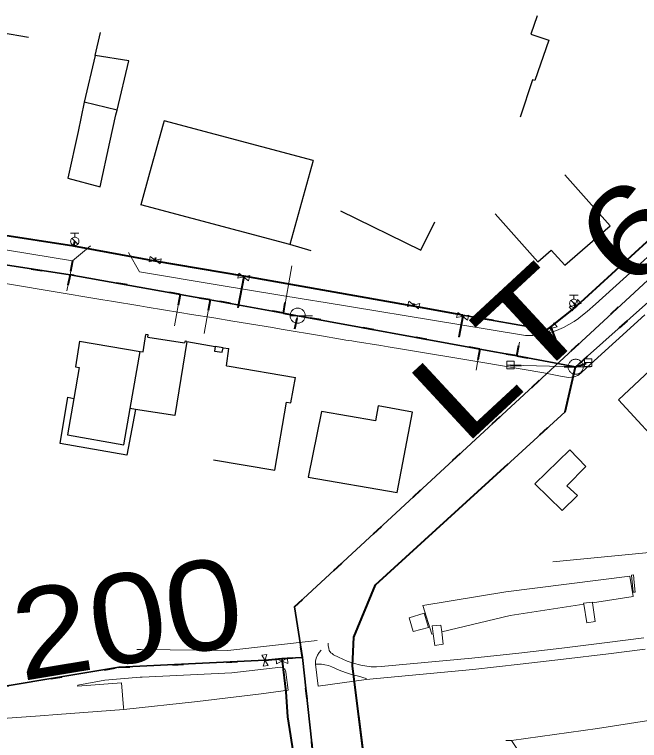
# Model space of a CAD drawing. Extents: x -968691 to -140888, y -1376050 to -879856.
# Drawn here: x -646241.5 to -646158, y -1062373.4 to -1062276.4 of the extents above; entities that cross this region are included whole.
import ezdxf
from ezdxf.enums import TextEntityAlignment as Align

# ---------------------------------------------------------------- set-up
doc = ezdxf.new("R2010")
doc.units = 0
doc.header["$LTSCALE"] = 4.8
for name, pattern in [('DASH_DOUBLE_DOT', [9.2, 5, -1.2, 0.3, -1.2, 0.3, -1.2]), ('DOT_DASHED', [7.7, 5, -1.2, 0.3, -1.2]), ('DOTTED', [1.5, 0.3, -1.2]), ('MEDIUM_DASHED', [4.5, 3, -1.5])]:
    doc.linetypes.add(name, pattern=pattern)
doc.layers.add('1', color=7, linetype='Continuous', lineweight=13)

msp = doc.modelspace()

# ---------------------------------------------------------------- linework, layer by layer
at = {"layer": '1', "lineweight": 25}
for p, q in [((-646171.665, -1062276.578), (-646172.486, -1062279.028)), ((-646239.603, -1062279.467), (-646243.221, -1062278.852)), ((-646230.719, -1062281.88), (-646232.163, -1062288.081)), ((-646227.78, -1062289.17), (-646226.21, -1062282.57)), ((-646232.163, -1062288.081), (-646232.97, -1062292.03)), ((-646227.78, -1062289.17), (-646232.163, -1062288.081)), ((-646221.476, -1062290.589), (-646221.606, -1062291.056)), ((-646201.572, -1062295.897), (-646221.476, -1062290.589)), ((-646232.97, -1062292.03), (-646234.36, -1062298.26)), ((-646171.573, -1062309.427), (-646177.286, -1062303.049)), ((-646171.573, -1062309.427), (-646169.805, -1062307.874)), ((-646169.805, -1062307.874), (-646167.951, -1062309.912)), ((-646224.288, -1062321.503), (-646223.931, -1062319.163)), ((-646223.617, -1062319.212), (-646223.931, -1062319.163)), ((-646223.668, -1062319.536), (-646223.617, -1062319.212)), ((-646232.786, -1062320.069), (-646233.36, -1062323.471)), ((-646232.786, -1062320.069), (-646224.721, -1062321.436)), ((-646223.668, -1062319.536), (-646218.77, -1062320.283)), ((-646218.447, -1062320.109), (-646214.664, -1062320.754)), ((-646213.617, -1062320.926), (-646212.864, -1062321.049)), ((-646213.185, -1062323.337), (-646212.864, -1062321.049)), ((-646226.044, -1062329.06), (-646224.721, -1062321.436)), ((-646224.721, -1062321.436), (-646224.288, -1062321.503)), ((-646233.36, -1062323.471), (-646232.857, -1062323.556)), ((-646213.185, -1062323.337), (-646212.802, -1062323.403)), ((-646212.802, -1062323.403), (-646203.969, -1062324.919)), ((-646204.553, -1062328.322), (-646203.969, -1062324.919)), ((-646188.298, -1062329.557), (-646192.897, -1062328.701)), ((-646190.36, -1062340.311), (-646188.298, -1062329.557)), ((-646165.164, -1062336.821), (-646167.692, -1062339.399)), ((-646202.24, -1062338.236), (-646190.36, -1062340.311)), ((-646168.342, -1062342.714), (-646171.987, -1062339.12)), ((-646167.692, -1062339.399), (-646166.28, -1062340.673)), ((-646166.28, -1062340.673), (-646168.342, -1062342.714))]:
    msp.add_line(p, q, dxfattribs=at)
at = {"layer": '1', "linetype": 'DASH_DOUBLE_DOT', "lineweight": 40}
for p, q in [((-646149.859, -1062300.177), (-646166.409, -1062315.397)), ((-646233.574, -1062307.333), (-646258.8, -1062303.433)), ((-646233.574, -1062307.333), (-646233.431, -1062306.701)), ((-646188.207, -1062315.382), (-646188.159, -1062315.216)), ((-646188.159, -1062315.216), (-646188.148, -1062314.999)), ((-646166.591, -1062315.224), (-646166.761, -1062314.99)), ((-646166.409, -1062315.397), (-646166.591, -1062315.224)), ((-646166.409, -1062315.397), (-646169.876, -1062318.14)), ((-646167.92, -1062329.51), (-646166.52, -1062323.48)), ((-646193.27, -1062352.65), (-646167.92, -1062329.51)), ((-646196.17, -1062359.61), (-646193.27, -1062352.65)), ((-646196.35, -1062363.51), (-646196.17, -1062359.61)), ((-646208.022, -1062362.721), (-646205.775, -1062362.467)), ((-646205.775, -1062362.467), (-646205.745, -1062362.827)), ((-646193.66, -1062384.43), (-646196.35, -1062363.51))]:
    msp.add_line(p, q, dxfattribs=at)
at = {"layer": '1', "lineweight": 35}
for p, q in [((-646149.859, -1062300.177), (-646166.409, -1062315.397)), ((-646233.574, -1062307.333), (-646258.8, -1062303.433)), ((-646246.38, -1062309.307), (-646234.073, -1062311.166)), ((-646154.258, -1062312.527), (-646166.52, -1062323.48)), ((-646205.565, -1062316.306), (-646215.343, -1062314.543)), ((-646205.565, -1062316.306), (-646203.663, -1062316.649)), ((-646166.409, -1062315.397), (-646169.876, -1062318.14)), ((-646179.311, -1062321.128), (-646203.663, -1062316.649)), ((-646174.364, -1062322.037), (-646179.311, -1062321.128)), ((-646174.364, -1062322.037), (-646166.52, -1062323.48)), ((-646205.775, -1062362.467), (-646203.013, -1062362.334))]:
    msp.add_line(p, q, dxfattribs=at)
at = {"layer": '1'}
for p, q in [((-646233.99, -1062305.632), (-646232.872, -1062305.632)), ((-646233.431, -1062306.143), (-646233.431, -1062305.632)), ((-646233.036, -1062307.097), (-646233.826, -1062306.306)), ((-646233.744, -1062309.318), (-646231.323, -1062307.33)), ((-646233.574, -1062307.333), (-646233.431, -1062306.701)), ((-646233.744, -1062309.318), (-646234.073, -1062311.166)), ((-646205.565, -1062316.306), (-646204.425, -1062309.985)), ((-646234.073, -1062311.166), (-646234.491, -1062313.345)), ((-646219.353, -1062313.82), (-646220.11, -1062318.018)), ((-646167.32, -1062313.921), (-646166.202, -1062313.921)), ((-646166.761, -1062314.432), (-646166.761, -1062313.921)), ((-646215.343, -1062314.543), (-646216.152, -1062319.027)), ((-646188.207, -1062315.382), (-646188.159, -1062315.216)), ((-646188.159, -1062315.216), (-646188.148, -1062314.999)), ((-646166.366, -1062315.386), (-646167.156, -1062314.595)), ((-646166.591, -1062315.224), (-646166.761, -1062314.99)), ((-646166.409, -1062315.397), (-646166.591, -1062315.224)), ((-646204.671, -1062316.649), (-646201.695, -1062316.649)), ((-646204.033, -1062318.409), (-646203.663, -1062316.649)), ((-646157.274, -1062316.536), (-646165.032, -1062323.593)), ((-646174.364, -1062322.037), (-646174.022, -1062320.175)), ((-646179.311, -1062321.128), (-646179.825, -1062323.921)), ((-646170.758, -1062324.308), (-646179.169, -1062322.869)), ((-646165.349, -1062322.921), (-646164.349, -1062322.921)), ((-646175.73, -1062323.25), (-646174.73, -1062323.25)), ((-646167.528, -1062323.48), (-646164.552, -1062323.48)), ((-646165.032, -1062323.593), (-646165.807, -1062324.324)), ((-646145.858, -1062347.238), (-646169.578, -1062349.572)), ((-646175.838, -1062353.59), (-646159.28, -1062351.494)), ((-646159.28, -1062351.494), (-646158.831, -1062354.207)), ((-646186.957, -1062355.413), (-646175.838, -1062353.59)), ((-646158.831, -1062354.207), (-646164.264, -1062355.04)), ((-646185.752, -1062359.219), (-646186.957, -1062355.413)), ((-646165.431, -1062355.219), (-646175.257, -1062356.726)), ((-646175.257, -1062356.726), (-646184.402, -1062358.898)), ((-646185.548, -1062359.17), (-646185.752, -1062359.219)), ((-646157.4, -1062359.7), (-646162.33, -1062360.33)), ((-646201.073, -1062360.077), (-646212.968, -1062361.433)), ((-646162.33, -1062360.33), (-646168.35, -1062361.09)), ((-646224.563, -1062361.28), (-646225.128, -1062361.273)), ((-646212.968, -1062361.433), (-646224.563, -1062361.28)), ((-646174.13, -1062361.75), (-646180.4, -1062362.43)), ((-646168.35, -1062361.09), (-646174.13, -1062361.75)), ((-646162.15, -1062361.85), (-646168.16, -1062362.59)), ((-646157.21, -1062361.23), (-646162.15, -1062361.85)), ((-646205.775, -1062362.467), (-646205.745, -1062362.827)), ((-646180.4, -1062362.43), (-646192.51, -1062363.57)), ((-646168.16, -1062362.59), (-646173.92, -1062363.26)), ((-646205.921, -1062363.644), (-646212.46, -1062364.385)), ((-646200.923, -1062366.187), (-646201.289, -1062363.243)), ((-646173.92, -1062363.26), (-646180.27, -1062363.94)), ((-646212.46, -1062364.385), (-646224.434, -1062364.974)), ((-646205.246, -1062364.293), (-646204.905, -1062366.714)), ((-646180.27, -1062363.94), (-646194.49, -1062365.29)), ((-646200.923, -1062366.187), (-646194.49, -1062365.29)), ((-646226.9, -1062369.316), (-646217.04, -1062368.217)), ((-646235.806, -1062369.99), (-646226.9, -1062369.316)), ((-646247.414, -1062370.785), (-646238.073, -1062370.161)), ((-646238.073, -1062370.161), (-646235.806, -1062369.99))]:
    msp.add_line(p, q, dxfattribs=at)
at = {"layer": '1', "linetype": 'MEDIUM_DASHED', "lineweight": 25}
for p, q in [((-646201.861, -1062307.959), (-646204.716, -1062307.146)), ((-646213.617, -1062320.926), (-646214.664, -1062320.754)), ((-646234.356, -1062327.558), (-646233.571, -1062327.704)), ((-646225.326, -1062329.193), (-646226.464, -1062335.317)), ((-646225.326, -1062329.193), (-646226.044, -1062329.06))]:
    msp.add_line(p, q, dxfattribs=at)
at = {"layer": '1', "linetype": 'DOTTED', "lineweight": 40}
for p, q in [((-646246.38, -1062309.307), (-646234.073, -1062311.166)), ((-646233.744, -1062309.318), (-646234.073, -1062311.166)), ((-646205.565, -1062316.306), (-646204.425, -1062309.985)), ((-646234.073, -1062311.166), (-646234.491, -1062313.345)), ((-646154.258, -1062312.527), (-646166.52, -1062323.48)), ((-646219.353, -1062313.82), (-646220.11, -1062318.018)), ((-646215.343, -1062314.543), (-646216.152, -1062319.027)), ((-646205.565, -1062316.306), (-646215.343, -1062314.543)), ((-646205.565, -1062316.306), (-646203.663, -1062316.649)), ((-646204.033, -1062318.409), (-646203.663, -1062316.649)), ((-646179.311, -1062321.128), (-646203.663, -1062316.649)), ((-646174.364, -1062322.037), (-646174.022, -1062320.175)), ((-646179.311, -1062321.128), (-646179.825, -1062323.921)), ((-646174.364, -1062322.037), (-646179.311, -1062321.128)), ((-646174.364, -1062322.037), (-646166.52, -1062323.48)), ((-646205.775, -1062362.467), (-646203.013, -1062362.334)), ((-646200.051, -1062389.37), (-646203.013, -1062362.334))]:
    msp.add_line(p, q, dxfattribs=at)
at = {"layer": '1', "linetype": 'DOT_DASHED', "lineweight": 25}
for p, q in [((-646214.664, -1062320.754), (-646214.759, -1062321.399)), ((-646213.736, -1062321.547), (-646213.617, -1062320.926)), ((-646214.759, -1062321.399), (-646213.736, -1062321.547))]:
    msp.add_line(p, q, dxfattribs=at)
at = {"layer": '1', "linetype": 'MEDIUM_DASHED', "lineweight": 35}
for p, q in [((-646167.92, -1062329.51), (-646166.52, -1062323.48)), ((-646193.27, -1062352.65), (-646167.92, -1062329.51)), ((-646196.17, -1062359.61), (-646193.27, -1062352.65)), ((-646196.35, -1062363.51), (-646196.17, -1062359.61))]:
    msp.add_line(p, q, dxfattribs=at)
at = {"layer": '1', "linetype": 'DOTTED', "lineweight": 40}
for points in [[(-646203.013, -1062362.334), (-646204.087, -1062355.591), (-646116.192, -1062274.176)], [(-646215.343, -1062314.543), (-646219.353, -1062313.82), (-646234.073, -1062311.166)], [(-646169.876, -1062318.14), (-646170.398, -1062318.56), (-646181.582, -1062316.571)], [(-646175.23, -1062323.25), (-646166.52, -1062323.48), (-646164.849, -1062322.921)], [(-646250.776, -1062367.517), (-646227.54, -1062363.659), (-646208.022, -1062362.721)]]:
    msp.add_lwpolyline(points, dxfattribs=at)
at = {"layer": '1', "lineweight": 35}
for points in [[(-646203.013, -1062362.334), (-646204.087, -1062355.591), (-646116.192, -1062274.176)], [(-646210.841, -1062311.363), (-646222.697, -1062309.371), (-646233.574, -1062307.333)], [(-646215.343, -1062314.543), (-646219.353, -1062313.82), (-646234.073, -1062311.166)], [(-646169.876, -1062318.14), (-646170.398, -1062318.56), (-646181.582, -1062316.571), (-646188.207, -1062315.382), (-646210.841, -1062311.363)], [(-646250.776, -1062367.517), (-646227.54, -1062363.659), (-646208.022, -1062362.721), (-646205.775, -1062362.467)], [(-646163.658, -1062633.108), (-646166.78, -1062613.779), (-646170.944, -1062588.372), (-646173.336, -1062572.987), (-646174.283, -1062562.133), (-646181.259, -1062514.067), (-646183, -1062500.862), (-646184.952, -1062489.727), (-646187.355, -1062471.952), (-646188.163, -1062467.368), (-646192.754, -1062436.977), (-646194.767, -1062423.918), (-646197.934, -1062403.993), (-646200.051, -1062389.37), (-646203.013, -1062362.334)]]:
    msp.add_lwpolyline(points, dxfattribs=at)
at = {"layer": '1', "lineweight": 25}
for points in [[(-646226.21, -1062282.57), (-646230.719, -1062281.88), (-646230.014, -1062278.805)], [(-646172.486, -1062279.028), (-646170.121, -1062279.821), (-646171.978, -1062285.193), (-646172.274, -1062285.126), (-646173.949, -1062290.125)], [(-646228.76, -1062293.43), (-646227.93, -1062289.78), (-646227.78, -1062289.17)], [(-646221.606, -1062291.056), (-646223.431, -1062297.582), (-646224.62, -1062301.838)], [(-646234.36, -1062298.26), (-646230.061, -1062299.403), (-646228.76, -1062293.43)], [(-646201.572, -1062295.897), (-646204.716, -1062307.146), (-646224.62, -1062301.838)], [(-646167.951, -1062309.912), (-646161.923, -1062304.62), (-646167.973, -1062297.824)], [(-646197.939, -1062302.651), (-646187.188, -1062307.907), (-646185.316, -1062304.09)], [(-646218.447, -1062320.109), (-646220.049, -1062329.991), (-646225.326, -1062329.193)], [(-646218.447, -1062320.109), (-646218.708, -1062320.053), (-646218.77, -1062320.283)], [(-646154.073, -1062335.203), (-646160.786, -1062327.92), (-646153.81, -1062321.348)], [(-646232.857, -1062323.556), (-646233.571, -1062327.704), (-646234.41, -1062332.575), (-646226.89, -1062333.933), (-646226.044, -1062329.06)], [(-646214.891, -1062335.902), (-646206.716, -1062337.286), (-646205.163, -1062328.217), (-646204.553, -1062328.322)], [(-646192.897, -1062328.701), (-646193.263, -1062330.694), (-646200.495, -1062329.447), (-646202.24, -1062338.236)], [(-646171.987, -1062339.12), (-646167.318, -1062334.595), (-646165.164, -1062336.821)]]:
    msp.add_lwpolyline(points, dxfattribs=at)
at = {"layer": '1'}
for points in [[(-646166.062, -1062316.93), (-646164.978, -1062316.111), (-646163.869, -1062315.12), (-646157.426, -1062309.252), (-646149.103, -1062301.676), (-646143.832, -1062296.861)], [(-646258.703, -1062301.449), (-646258.683, -1062301.767), (-646258.572, -1062302.212), (-646258.272, -1062303.02), (-646257.788, -1062303.975), (-646257.294, -1062304.622), (-646256.702, -1062305.143), (-646256.086, -1062305.503), (-646255.105, -1062305.789), (-646248.165, -1062306.931), (-646233.744, -1062309.318)], [(-646226.265, -1062308.201), (-646224.788, -1062310.781), (-646213.883, -1062312.598), (-646202.804, -1062314.428)], [(-646222.697, -1062309.371), (-646222.698, -1062309.24), (-646222.602, -1062308.884)], [(-646179.169, -1062322.869), (-646189.667, -1062321.113), (-646191.577, -1062320.795), (-646192.555, -1062320.632), (-646195.97, -1062320.105), (-646196.441, -1062320.023), (-646197.21, -1062319.915), (-646197.69, -1062319.815), (-646197.941, -1062319.789), (-646200.466, -1062319.323), (-646205.861, -1062318.472), (-646207.037, -1062318.247), (-646212.304, -1062317.373), (-646214.858, -1062316.953), (-646217.83, -1062316.479), (-646219.418, -1062316.243), (-646223.768, -1062315.506), (-646224.741, -1062315.339), (-646228.531, -1062314.688), (-646229.679, -1062314.515), (-646236.575, -1062313.379), (-646246.967, -1062311.637), (-646255.824, -1062310.17)], [(-646210.841, -1062311.363), (-646210.862, -1062311.467), (-646211.635, -1062315.586)], [(-646202.804, -1062314.428), (-646199.982, -1062314.89), (-646182.145, -1062317.836), (-646173.227, -1062319.294), (-646172.228, -1062319.286), (-646171.531, -1062319.186), (-646171.057, -1062319.117), (-646169.764, -1062318.864), (-646169.091, -1062318.626), (-646168.154, -1062318.232), (-646167.413, -1062317.844), (-646166.728, -1062317.414)], [(-646181.582, -1062316.571), (-646181.61, -1062316.732), (-646182.11, -1062319.516)], [(-646166.728, -1062317.414), (-646166.16, -1062317.02), (-646166.062, -1062316.93)], [(-646169.876, -1062318.14), (-646169.784, -1062318.331), (-646168.842, -1062320.757)], [(-646175.23, -1062323.25), (-646166.52, -1062323.48), (-646164.849, -1062322.921)], [(-646165.807, -1062324.324), (-646166.238, -1062324.647), (-646166.734, -1062324.843), (-646167.451, -1062324.902), (-646168.302, -1062324.767), (-646170.758, -1062324.308)], [(-646192.51, -1062363.57), (-646193.13, -1062363.62), (-646193.84, -1062363.58), (-646194.69, -1062363.47), (-646195.23, -1062363.38), (-646196.24, -1062363.11), (-646197.03, -1062362.82), (-646198.19, -1062362.31), (-646198.86, -1062361.98), (-646199.05, -1062361.83), (-646199.22, -1062361.71), (-646199.43, -1062361.41), (-646199.49, -1062361.14), (-646199.57, -1062360.76), (-646199.604, -1062360.421)], [(-646201.289, -1062363.243), (-646201.289, -1062363.243), (-646201.272, -1062362.828), (-646201.182, -1062362.427), (-646201.019, -1062362.04), (-646200.792, -1062361.693), (-646200.507, -1062361.391)], [(-646205.745, -1062362.827), (-646205.243, -1062366.951), (-646205.026, -1062370.302), (-646204.002, -1062376.848), (-646203.076, -1062378.145), (-646200.843, -1062379.058), (-646194.773, -1062378.734), (-646185.846, -1062378.23), (-646182.438, -1062378.221), (-646174.102, -1062378.122), (-646172.499, -1062378.674), (-646170.509, -1062381.413), (-646170.109, -1062384.533)], [(-646205.921, -1062363.644), (-646205.721, -1062363.683), (-646205.54, -1062363.776), (-646205.51, -1062363.799), (-646205.393, -1062363.917), (-646205.292, -1062364.095), (-646205.246, -1062364.293)], [(-646194.49, -1062365.29), (-646194.49, -1062365.14), (-646195.51, -1062364.84), (-646196.48, -1062364.62), (-646197.25, -1062364.35), (-646198.11, -1062364.03), (-646199.1, -1062363.6), (-646199.55, -1062363.42), (-646200.05, -1062363.31), (-646200.48, -1062363.23), (-646201.289, -1062363.243)], [(-646224.434, -1062364.974), (-646224.711, -1062364.987), (-646229.416, -1062365.384), (-646233.039, -1062366.045), (-646233.086, -1062366.167), (-646227.197, -1062365.757)], [(-646227.197, -1062365.757), (-646226.936, -1062369.047), (-646226.9, -1062369.316)], [(-646217.04, -1062368.217), (-646208.529, -1062367.196), (-646204.905, -1062366.714)], [(-646175.09, -1062373.43), (-646163.621, -1062371.821), (-646144.79, -1062368.916)], [(-646175.86, -1062373.46), (-646175.09, -1062373.43), (-646173.01, -1062376.61), (-646172.003, -1062384.884)]]:
    msp.add_lwpolyline(points, dxfattribs=at)
for points in [[(-646232.872, -1062306.702), (-646232.881, -1062306.605), (-646232.906, -1062306.511), (-646232.947, -1062306.423), (-646233.003, -1062306.343), (-646233.072, -1062306.274), (-646233.152, -1062306.218), (-646233.24, -1062306.177), (-646233.334, -1062306.152), (-646233.431, -1062306.143), (-646233.528, -1062306.152), (-646233.622, -1062306.177), (-646233.71, -1062306.218), (-646233.79, -1062306.274), (-646233.859, -1062306.343), (-646233.915, -1062306.423), (-646233.956, -1062306.511), (-646233.981, -1062306.605), (-646233.99, -1062306.702), (-646233.981, -1062306.799), (-646233.956, -1062306.893), (-646233.915, -1062306.981), (-646233.859, -1062307.061), (-646233.79, -1062307.13), (-646233.71, -1062307.186), (-646233.622, -1062307.227), (-646233.528, -1062307.252), (-646233.431, -1062307.26), (-646233.334, -1062307.252), (-646233.24, -1062307.227), (-646233.152, -1062307.186), (-646233.072, -1062307.13), (-646233.003, -1062307.061), (-646232.947, -1062306.981), (-646232.906, -1062306.893), (-646232.881, -1062306.799)], [(-646221.895, -1062309.038), (-646222.028, -1062309.725), (-646223.368, -1062308.755), (-646223.501, -1062309.442)], [(-646210.054, -1062311.287), (-646210.205, -1062311.971), (-646211.519, -1062310.963), (-646211.67, -1062311.647)], [(-646187.354, -1062315.025), (-646187.495, -1062315.711), (-646188.823, -1062314.721), (-646188.964, -1062315.407)], [(-646166.931, -1062315.979), (-646167.388, -1062315.448), (-646165.794, -1062315), (-646166.251, -1062314.469)], [(-646166.202, -1062314.991), (-646166.211, -1062314.894), (-646166.236, -1062314.8), (-646166.277, -1062314.712), (-646166.333, -1062314.632), (-646166.402, -1062314.563), (-646166.482, -1062314.507), (-646166.57, -1062314.466), (-646166.664, -1062314.441), (-646166.761, -1062314.432), (-646166.858, -1062314.441), (-646166.952, -1062314.466), (-646167.04, -1062314.507), (-646167.12, -1062314.563), (-646167.189, -1062314.632), (-646167.245, -1062314.712), (-646167.286, -1062314.8), (-646167.311, -1062314.894), (-646167.32, -1062314.991), (-646167.311, -1062315.088), (-646167.286, -1062315.182), (-646167.245, -1062315.27), (-646167.189, -1062315.35), (-646167.12, -1062315.419), (-646167.04, -1062315.475), (-646166.952, -1062315.516), (-646166.858, -1062315.541), (-646166.761, -1062315.549), (-646166.664, -1062315.541), (-646166.57, -1062315.516), (-646166.482, -1062315.475), (-646166.402, -1062315.419), (-646166.333, -1062315.35), (-646166.277, -1062315.27), (-646166.236, -1062315.182), (-646166.211, -1062315.088)], [(-646203.663, -1062315.641), (-646203.768, -1062315.647), (-646203.872, -1062315.663), (-646203.974, -1062315.691), (-646204.073, -1062315.729), (-646204.167, -1062315.776), (-646204.255, -1062315.834), (-646204.337, -1062315.9), (-646204.412, -1062315.975), (-646204.478, -1062316.057), (-646204.536, -1062316.145), (-646204.583, -1062316.239), (-646204.621, -1062316.338), (-646204.649, -1062316.44), (-646204.665, -1062316.544), (-646204.671, -1062316.649), (-646204.665, -1062316.754), (-646204.649, -1062316.859), (-646204.621, -1062316.961), (-646204.583, -1062317.059), (-646204.536, -1062317.153), (-646204.478, -1062317.242), (-646204.412, -1062317.324), (-646204.337, -1062317.398), (-646204.255, -1062317.464), (-646204.167, -1062317.522), (-646204.073, -1062317.57), (-646203.974, -1062317.608), (-646203.872, -1062317.635), (-646203.768, -1062317.651), (-646203.663, -1062317.657), (-646203.558, -1062317.651), (-646203.453, -1062317.635), (-646203.351, -1062317.608), (-646203.253, -1062317.57), (-646203.159, -1062317.522), (-646203.07, -1062317.464), (-646202.988, -1062317.398), (-646202.914, -1062317.324), (-646202.848, -1062317.242), (-646202.79, -1062317.153), (-646202.742, -1062317.059), (-646202.704, -1062316.961), (-646202.677, -1062316.859), (-646202.661, -1062316.754), (-646202.655, -1062316.649), (-646202.661, -1062316.544), (-646202.677, -1062316.44), (-646202.704, -1062316.338), (-646202.742, -1062316.239), (-646202.79, -1062316.145), (-646202.848, -1062316.057), (-646202.914, -1062315.975), (-646202.988, -1062315.9), (-646203.07, -1062315.834), (-646203.159, -1062315.776), (-646203.253, -1062315.729), (-646203.351, -1062315.691), (-646203.453, -1062315.663), (-646203.558, -1062315.647)], [(-646180.8, -1062316.564), (-646180.961, -1062317.245), (-646182.259, -1062316.219), (-646182.42, -1062316.9)], [(-646170.147, -1062319.075), (-646170.587, -1062318.53), (-646168.981, -1062318.132), (-646169.421, -1062317.587)], [(-646175.73, -1062323.75), (-646174.73, -1062323.75), (-646174.73, -1062322.75), (-646175.73, -1062322.75)], [(-646166.52, -1062322.472), (-646166.625, -1062322.478), (-646166.729, -1062322.494), (-646166.831, -1062322.522), (-646166.93, -1062322.56), (-646167.024, -1062322.607), (-646167.112, -1062322.665), (-646167.194, -1062322.731), (-646167.269, -1062322.806), (-646167.335, -1062322.888), (-646167.393, -1062322.976), (-646167.44, -1062323.07), (-646167.478, -1062323.169), (-646167.506, -1062323.271), (-646167.522, -1062323.375), (-646167.528, -1062323.48), (-646167.522, -1062323.585), (-646167.506, -1062323.69), (-646167.478, -1062323.792), (-646167.44, -1062323.89), (-646167.393, -1062323.984), (-646167.335, -1062324.073), (-646167.269, -1062324.155), (-646167.194, -1062324.229), (-646167.112, -1062324.295), (-646167.024, -1062324.353), (-646166.93, -1062324.401), (-646166.831, -1062324.439), (-646166.729, -1062324.466), (-646166.625, -1062324.482), (-646166.52, -1062324.488), (-646166.415, -1062324.482), (-646166.31, -1062324.466), (-646166.208, -1062324.439), (-646166.11, -1062324.401), (-646166.016, -1062324.353), (-646165.927, -1062324.295), (-646165.845, -1062324.229), (-646165.771, -1062324.155), (-646165.705, -1062324.073), (-646165.647, -1062323.984), (-646165.599, -1062323.89), (-646165.561, -1062323.792), (-646165.534, -1062323.69), (-646165.518, -1062323.585), (-646165.512, -1062323.48), (-646165.518, -1062323.375), (-646165.534, -1062323.271), (-646165.561, -1062323.169), (-646165.599, -1062323.07), (-646165.647, -1062322.976), (-646165.705, -1062322.888), (-646165.771, -1062322.806), (-646165.845, -1062322.731), (-646165.927, -1062322.665), (-646166.016, -1062322.607), (-646166.11, -1062322.56), (-646166.208, -1062322.522), (-646166.31, -1062322.494), (-646166.415, -1062322.478)], [(-646165.349, -1062323.421), (-646164.349, -1062323.421), (-646164.349, -1062322.421), (-646165.349, -1062322.421)], [(-646158.817, -1062353.593), (-646159.048, -1062351.349), (-646158.81, -1062351.288), (-646158.71, -1062352.322), (-646158.586, -1062353.611)], [(-646165.04, -1062357.73), (-646163.91, -1062357.52), (-646164.264, -1062355.04), (-646164.28, -1062354.93), (-646165.45, -1062355.1), (-646165.431, -1062355.219)], [(-646188.242, -1062358.874), (-646188.765, -1062357.054), (-646186.767, -1062356.408), (-646186.197, -1062358.34)], [(-646184.51, -1062358.01), (-646185.7, -1062358.12), (-646185.548, -1062359.17), (-646185.32, -1062360.74), (-646184.2, -1062360.57), (-646184.402, -1062358.898)], [(-646207.581, -1062363.422), (-646208.276, -1062363.509), (-646207.768, -1062361.933), (-646208.463, -1062362.02)], [(-646205.015, -1062362.437), (-646204.977, -1062363.136), (-646206.513, -1062362.518), (-646206.475, -1062363.217)]]:
    msp.add_lwpolyline(points, close=True, dxfattribs=at)
at = {"layer": '1', "linetype": 'DASH_DOUBLE_DOT', "lineweight": 40}
for points in [[(-646210.841, -1062311.363), (-646222.697, -1062309.371), (-646233.574, -1062307.333)], [(-646222.697, -1062309.371), (-646222.698, -1062309.24), (-646222.602, -1062308.884)], [(-646210.841, -1062311.363), (-646210.862, -1062311.467), (-646211.635, -1062315.586)], [(-646181.582, -1062316.571), (-646188.207, -1062315.382), (-646210.841, -1062311.363)], [(-646181.582, -1062316.571), (-646181.61, -1062316.732), (-646182.11, -1062319.516)], [(-646169.876, -1062318.14), (-646169.784, -1062318.331), (-646168.842, -1062320.757)], [(-646205.745, -1062362.827), (-646205.243, -1062366.951), (-646205.026, -1062370.302), (-646204.002, -1062376.848), (-646203.076, -1062378.145), (-646200.843, -1062379.058), (-646194.773, -1062378.734), (-646185.846, -1062378.23), (-646182.438, -1062378.221), (-646174.102, -1062378.122), (-646172.499, -1062378.674), (-646170.509, -1062381.413), (-646170.109, -1062384.533)]]:
    msp.add_lwpolyline(points, dxfattribs=at)
at = {"layer": '1', "linetype": 'MEDIUM_DASHED', "lineweight": 25}
msp.add_lwpolyline([(-646226.464, -1062335.317), (-646235.408, -1062333.72), (-646234.356, -1062327.558)], dxfattribs=at)
at = {"layer": '1', "linetype": 'MEDIUM_DASHED', "lineweight": 35}
msp.add_lwpolyline([(-646193.49, -1062385.24), (-646193.66, -1062384.43), (-646196.35, -1062363.51)], dxfattribs=at)
at = {"layer": '1'}
for centre in [(-646222.698, -1062309.24), (-646210.862, -1062311.467), (-646188.159, -1062315.216), (-646166.591, -1062315.224), (-646181.61, -1062316.732), (-646169.784, -1062318.331), (-646208.022, -1062362.721), (-646205.745, -1062362.827)]:
    msp.add_circle(centre, 0.132, dxfattribs=at)

# ---------------------------------------------------------------- texts
for s, rotation, width, p in [('LT 600', 42.808, 1.3, (-646157.668, -1062312.185)), ('LT 200', 9.427, 1.15, (-646238.562, -1062365.185))]:
    msp.add_text(s, height=12, rotation=rotation, dxfattribs=dict(at, width=width)).set_placement(p, align=Align.CENTER)

doc.saveas('drawing.dxf')
